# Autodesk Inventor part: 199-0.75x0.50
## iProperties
Created: 2007-07
Part Number: 199-0.75x0.50
Document SubType Name: Modeling
Designer: btaylor
Density: 1 g/cm^3
Author: btaylor
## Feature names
1. Extrusion1
2. Extrusion2
3. Loft1
4. Loft2
5. Extrusion4
6. Extrusion5
7. Extrusion6
8. Extrusion7
9. Fillet1
10. Fillet2
11. Extrusion8
12. Extrusion9
13. Extrusion10
14. Chamfer1
15. Chamfer2
16. Chamfer3
17. Fillet3
18. Fillet4
19. Fillet5
20. Fillet6
21. Fillet7
22. Fillet9
23. Fillet10
24. Fillet11
